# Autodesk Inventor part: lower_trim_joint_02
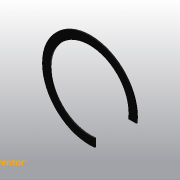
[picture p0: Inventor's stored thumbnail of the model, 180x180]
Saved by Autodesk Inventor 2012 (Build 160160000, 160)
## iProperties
Created: 2002-07
Part Number: lower_trim_joint_02
Description: Lower Trim Joint
Document SubType Name: Modeling
Designer: Lieven Grauls
Stock Number: lower_trim_joint_02
Project: Valve Techcamp 2008
Density: 1 g/cm^3
Mass: 0.857615 g
Surface Area: 22.0257 cm^2
Volume: 0.857615 cm^3
Material: Default
Company: Autodesk
Control State: 0
Master: False
Checked Out: False
Shininess: 64.0
Length Units: 11269
Angle Units: 11279
Time Units: 11290
Mass Units: 11283
Length Display Precision: 3
Angle Display Precision: 2
Density: 0.0
Volumn: 0.0
Area: 0.0
PropertySet Name: Model Information
Author: Lieven Grauls
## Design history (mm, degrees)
sketch "Sketch1"
  geometry: L1 (29, 0)-(35, 0); L2 (35, 0)-(35, 0.9); L3 (35, 0.9)-(29, 0.9); L4 (29, 0.9)-(29, 0); L5 (0, 1.08)-(0, -0.18) reference; 1 further point
  constraints: 8 end point, 2 parallel, 1 horizontal, 1 horizontal alignment, 1 perpendicular
  dimensions: "d0" = 58 diameter of L4 L5; "d1" = 70 diameter of L2 L5; "d2" = 0.9 distance between parallel lines of L1 L3
revolve "Revolution1" sketch "Sketch1" stored, may be unused: angle "d3" = 90 deg
sketch "Sketch2"
  geometry: L1 (0, 0)-(4, -28.723); L2 (0, 0)-(28.723, -4); L3 (0, 50.027)-(0, -55.161) reference; L4 (-50.027, 0)-(55.161, 0) reference; L5 (4, -28.723)-(4, -34.771); L6 (28.723, -4)-(34.771, -4); A1 r 35 centre (0, 0) between (4, -34.771) and (34.771, -4) reference; A2 r 35 centre (0, 0) between (4, -34.771) and (34.771, -4); A3 r 29 centre (0, 0) between (4, -28.723) and (28.723, -4) reference
  constraints: 8 end point, 6 point on circle, 2 perpendicular, 1 centre point, 1 coincident
  dimensions: "d8" = 4 distance between parallel lines of L5 L3; "d9" = 4 distance between parallel lines of L4 L6
extrude "Extrusion1" cut sketch "Sketch2" stored distance "d6" = 10; taper "d7" = 0 deg
node "Volumenkörper1"
node "Volumenkörpern"
node "Oberflächenkörpern"
